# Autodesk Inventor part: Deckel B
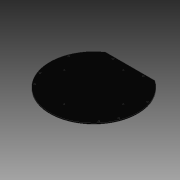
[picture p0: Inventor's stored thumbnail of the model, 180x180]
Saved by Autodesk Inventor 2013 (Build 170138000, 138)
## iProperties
Created: 2012-10
Part Number: Deckel B
Material: PMMA-Kunststoff
Document SubType Name: Modeling
Designer: SteffenHaase
Density: 1.188 g/cm^3
Mass: 44.3155 g
Surface Area: 383.274 cm^2
Volume: 37.3026 cm^3
Author: SteffenHaase
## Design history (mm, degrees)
sketch "Skizze1"
  geometry: L1 (-48.836, 72)-(48.836, 72); L2 (-52.206, 69.595)-(52.206, 69.595); A1 r 87 centre (0, 0) between (-48.836, 72) and (48.836, 72); A2 r 87 centre (0, 0) between (-52.206, 69.595) and (52.206, 69.595); 1 further point
  constraints: 4 end point, 4 point on circle, 2 centre point, 2 coincident, 1 horizontal, 1 parallel
  dimensions: "d0" = 174 diameter of A1; "d5" = 174 diameter of A2; "d7" = 72 distance from line of point (0, 0) L1
extrude "Extrusion1" new body sketch "Skizze1" distance "d3" = 1; taper "d4" = 0 deg
sketch "Skizze4"
  geometry: L1 (0, 0)-(-63.582, -53.351); L2 (0, 0)-(63.582, -53.351); L3 (-121.8, 0)-(121.8, 0) reference; L4 (0, 117)-(0, -121) reference; L5 (-30, 68)-(30, 68); A1 r 87 centre (0, 0) between (-48.836, 72) and (48.836, 72) reference; A2 r 83 centre (0, 0) between (-63.582, -53.351) and (63.582, -53.351); 4 further points
  constraints: 6 end point, 5 coincident, 2 point on circle, 1 centre point, 1 perpendicular, 1 symmetric about line
  dimensions: "d34" = 166 diameter of A2; "d35" = 40 deg angle of L1 L3; "d37" = 40 deg angle of L3 L2 (= d35); "d39" = 60 distance of L5.start L5.end; "d40" = 68 distance between parallel lines of L3 L5
hole "Bohrung3" sketch "Skizze4" at (-63.582, -53.351), (63.582, -53.351), (-30, 68), (30, 68) diameter "d41" = 3.2; stored, may be unused: countersink angle "d45" = 90 deg, drill point angle "d47" = 118 deg; dims "d42" = 6, "d43" = 4, "d44" = 2, "d46" = 8
sketch "Skizze5"
  geometry: L1 (0, 103.8)-(0, -118.8) reference; L2 (-121.8, 0)-(121.8, 0) reference; 3 further points
  constraints: 2 point on line, 1 symmetric about line
  dimensions: "d48" = 160 distance of point (80, 0) point (-80, 0)
hole "Bohrung4" sketch "Skizze5" at (-80, 0), (80, 0) diameter "d49" = 3.2; stored, may be unused: countersink angle "d53" = 90 deg, drill point angle "d55" = 118 deg; dims "d50" = 6, "d51" = 4, "d52" = 2, "d54" = 8
node "Volumenkörper1"
